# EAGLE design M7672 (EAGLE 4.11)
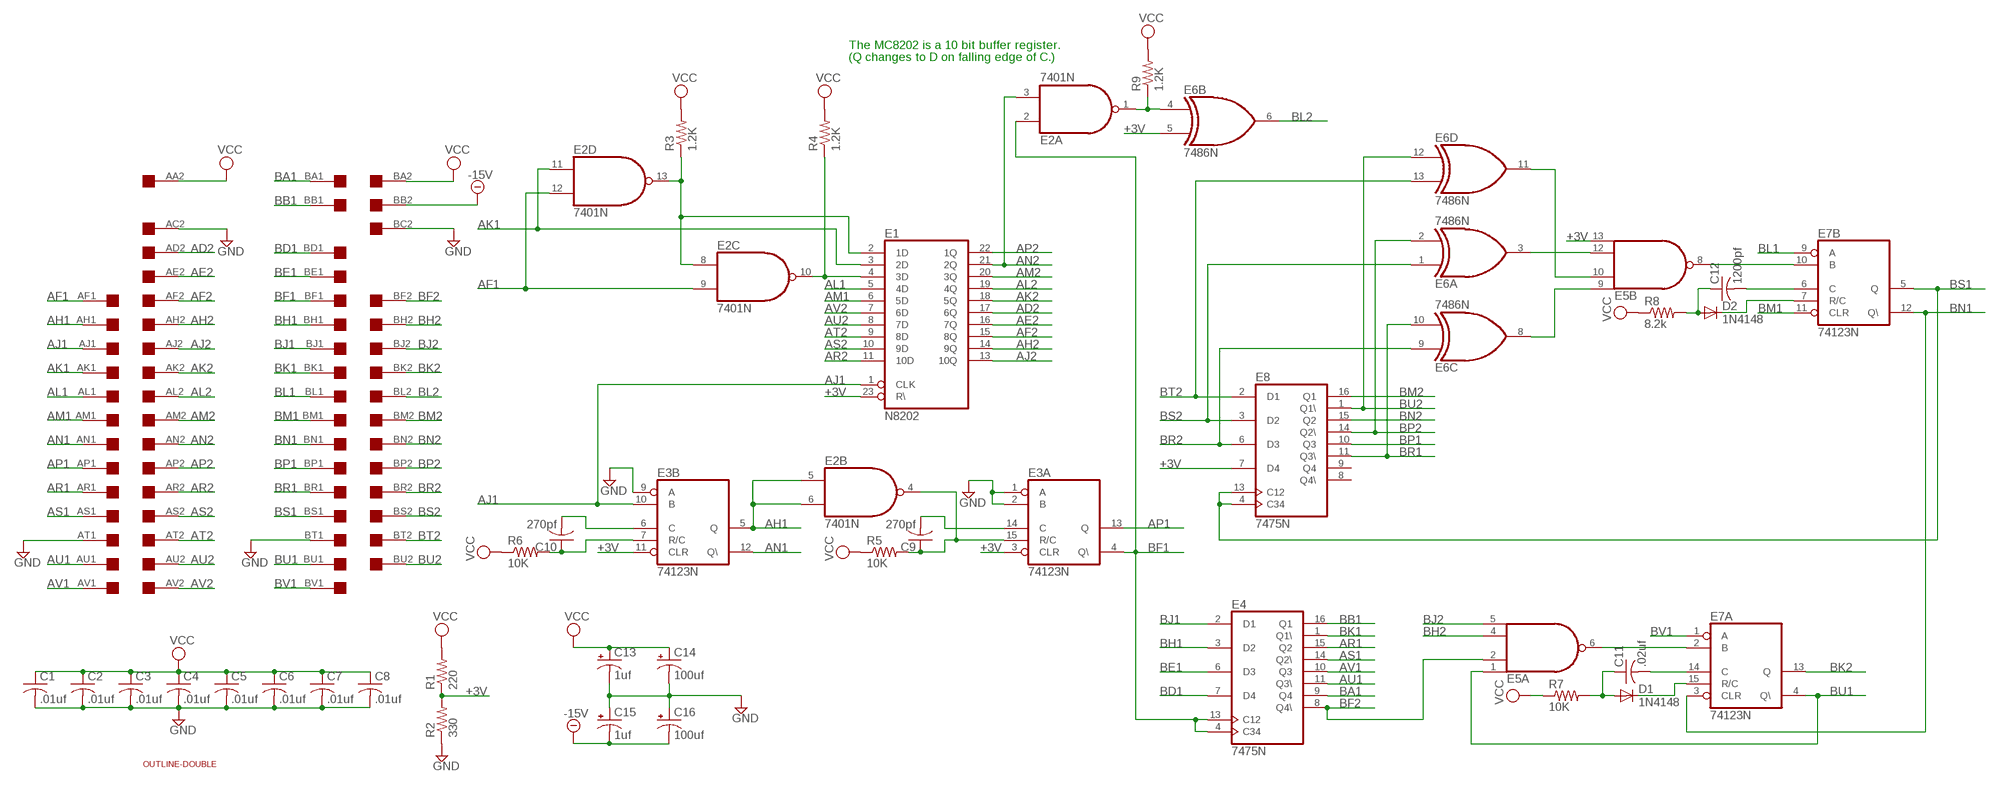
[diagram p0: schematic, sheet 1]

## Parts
C1  .01uf  C-US050-025X075  [C050-025X075]
C2  .01uf  C-US050-025X075  [C050-025X075]
C3  .01uf  C-US050-025X075  [C050-025X075]
C4  .01uf  C-US050-025X075  [C050-025X075]
C5  .01uf  C-US050-025X075  [C050-025X075]
C6  .01uf  C-US050-025X075  [C050-025X075]
C7  .01uf  C-US050-025X075  [C050-025X075]
C8  .01uf  C-US050-025X075  [C050-025X075]
C9  270pf  C-US050-025X075  [C050-025X075]
C10  270pf  C-US050-025X075  [C050-025X075]
C11  .02uf  C-US050-025X075  [C050-025X075]
C12  1200pf  C-US050-025X075  [C050-025X075]
C13  1uf  CPOL-USE30-10AXIAL  [E30-10]
C14  100uf  CPOL-USE30-10AXIAL  [E30-10]
C15  1uf  CPOL-USE30-10AXIAL  [E30-10]
C16  100uf  CPOL-USE30-10AXIAL  [E30-10]
D1  1N4148  [DO35-10]
D2  1N4148  [DO35-10]
E1  N8202  [DIL24]
E2  7401N  [DIL14]
E3  74123N  [DIL16]
E4  7475N  [DIL16]
E5  74S20N  [DIL14]
E6  7486N  [DIL14]
E7  74123N  [DIL16]
E8  7475N  [DIL16]
EDGE  DOUBLE  [EDGE-CON4]
R1  220  R-US_0207/10  [0207/10]
R2  330  R-US_0207/10  [0207/10]
R3  1.2K  R-US_0207/10  [0207/10]
R4  1.2K  R-US_0207/10  [0207/10]
R5  10K  R-US_0207/10  [0207/10]
R6  10K  R-US_0207/10  [0207/10]
R7  10K  R-US_0207/10  [0207/10]
R8  8.2k  R-US_0207/10  [0207/10]
R9  1.2K  R-US_0207/10  [0207/10]
U$2  OUTLINE-DOUBLE  [DOUBLE]

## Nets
+3V: E1.23(R\) E3.3(A:CLR) E3.11(B:CLR) E5.13(B:I3) E6.5(B:I1) E8.7(D4) R1.1 R2.2
-15V: C15.- C16.- EDGE.BB2
AD2: E1.17(6Q) EDGE.AD2
AE2: E1.16(7Q) EDGE.AE2
AF1: E2.9(C:I1) E2.12(D:I1) EDGE.AF1
AF2: E1.15(8Q) EDGE.AF2
AH1: E2.5(B:I0) E2.6(B:I1) E3.5(B:Q) EDGE.AH1
AH2: E1.14(9Q) EDGE.AH2
AJ1: E1.1(CLK) E3.10(B:B) EDGE.AJ1
AJ2: E1.13(10Q) EDGE.AJ2
AK1: E1.3(2D) E2.11(D:I0) EDGE.AK1
AK2: E1.18(5Q) EDGE.AK2
AL1: E1.5(4D) EDGE.AL1
AL2: E1.19(4Q) EDGE.AL2
AM1: E1.6(5D) EDGE.AM1
AM2: E1.20(3Q) EDGE.AM2
AN1: E3.12(B:Q\) EDGE.AN1
AN2: E1.21(2Q) E2.3(A:I1) EDGE.AN2
AP1: E3.13(A:Q) EDGE.AP1
AP2: E1.22(1Q) EDGE.AP2
AR1: E4.15(Q2) EDGE.AR1
AR2: E1.11(10D) EDGE.AR2
AS1: E4.14(Q2\) EDGE.AS1
AS2: E1.10(9D) EDGE.AS2
AT2: E1.9(8D) EDGE.AT2
AU1: E4.11(Q3\) EDGE.AU1
AU2: E1.8(7D) EDGE.AU2
AV1: E4.10(Q3) EDGE.AV1
AV2: E1.7(6D) EDGE.AV2
BA1: E4.9(Q4) EDGE.BA1
BB1: E4.16(Q1) EDGE.BB1
BD1: E4.7(D4) EDGE.BD1
BE1: E4.6(D3) EDGE.BE1
BF1: E2.2(A:I0) E3.4(A:Q\) E4.4(C34) E4.13(C12) EDGE.BF1
BF2: E4.8(Q4\) E5.2(A:I1) EDGE.BF2
BH1: E4.3(D2) EDGE.BH1
BH2: E5.4(A:I2) EDGE.BH2
BJ1: E4.2(D1) EDGE.BJ1
BJ2: E5.5(A:I3) EDGE.BJ2
BK1: E4.1(Q1\) EDGE.BK1
BK2: E7.13(A:Q) EDGE.BK2
BL1: E7.9(B:A) EDGE.BL1
BL2: E6.6(B:O) EDGE.BL2
BM1: E7.11(B:CLR) EDGE.BM1
BM2: E8.16(Q1) EDGE.BM2
BN1: E7.3(A:CLR) E7.12(B:Q\) EDGE.BN1
BN2: E8.15(Q2) EDGE.BN2
BP1: E8.10(Q3) EDGE.BP1
BP2: E6.2(A:I1) E8.14(Q2\) EDGE.BP2
BR1: E6.10(C:I1) E8.11(Q3\) EDGE.BR1
BR2: E6.9(C:I0) E8.6(D3) EDGE.BR2
BS1: E7.5(B:Q) E8.4(C34) E8.13(C12) EDGE.BS1
BS2: E6.1(A:I0) E8.3(D2) EDGE.BS2
BT2: E6.13(D:I1) E8.2(D1) EDGE.BT2
BU1: E5.1(A:I0) E7.4(A:Q\) EDGE.BU1
BU2: E6.12(D:I0) E8.1(Q1\) EDGE.BU2
BV1: E7.1(A:A) EDGE.BV1
GND [power]: C1.2 C2.2 C3.2 C4.2 C5.2 C6.2 C7.2 C8.2 C13.- C14.- C15.+ C16.+ E3.1(A:A) E3.2(A:B) E3.9(B:A) EDGE.AC2 EDGE.AT1 EDGE.BC2 EDGE.BT1 R2.1
N$1: E1.2(1D) E2.8(C:I0) E2.13(D:O) R3.1
N$2: E1.4(3D) E2.10(C:O) R4.1
N$3: E2.1(A:O) E6.4(B:I0) R9.1
N$4: E5.12(B:I2) E6.3(A:O)
N$5: C10.1 E3.7(B:R/C) R6.2
N$6: C10.2 E3.6(B:C)
N$7: C9.1 E2.4(B:O) E3.15(A:R/C) R5.2
N$8: C9.2 E3.14(A:C)
N$9: E5.10(B:I1) E6.11(D:O)
N$10: E5.9(B:I0) E6.8(C:O)
N$12: E5.6(A:O) E7.2(A:B)
N$13: D1.C E7.15(A:R/C)
N$14: C11.2 E7.14(A:C)
N$15: C11.1 D1.A R7.2
N$16: E5.8(B:O) E7.10(B:B)
N$17: D2.C E7.7(B:R/C)
N$18: C12.2 E7.6(B:C)
N$19: C12.1 D2.A R8.2
VCC [power]: C1.1 C2.1 C3.1 C4.1 C5.1 C6.1 C7.1 C8.1 C13.+ C14.+ EDGE.AA2 EDGE.BA2 R1.2 R3.2 R4.2 R5.1 R6.1 R7.1 R8.1 R9.2
Unconnected: E8.8(Q4\) E8.9(Q4) EDGE.AA1 EDGE.AB1 EDGE.AB2 EDGE.AC1 EDGE.AD1 EDGE.AE1 EDGE.BC1 EDGE.BD2 EDGE.BE2 EDGE.BV2

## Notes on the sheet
- The MC8202 is a 10 bit buffer register.
- (Q changes to D on falling edge of C.)

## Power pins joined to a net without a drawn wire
GND: E1.12(GND) E2.7(P:GND) E3.8(P:GND) E4.12(GND) E5.7(P:GND) E6.7(P:GND) E7.8(P:GND) E8.12(GND)
VCC: E1.24(VCC) E2.14(P:VCC) E3.16(P:VCC) E4.5(VCC) E5.14(P:VCC) E6.14(P:VCC) E7.16(P:VCC) E8.5(VCC)

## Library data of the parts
C1-C12 = rcl:C-US: CAPACITOR, American symbol
C13-C16 = rcl:CPOL-US: POLARIZED CAPACITOR, American symbol
D1 D2 = diode:1N4148: DIODE
E1 = dec-con:N8202: 10 bit register
E2 = 74xx-jameco:74*01: Quad 2-input NAND gate, open collector
E3 E7 = 74xx-jameco:74*123: Retriggerable monostable MULTIVIBRATOR
E4 E8 = 74xx-jameco:74*75: 4-bit bistable LATCH
E5 = 74xx-jameco:74*20: Dual 4-input NAND gate
E6 = 74xx-jameco:74*86: Quad 2-input EXCLUSIV-OR (XOR) gate
EDGE = dec-con:DOUBLE: Double-Height DEC board
R1-R9 = rcl:R-US_: RESISTOR, American symbol
U$2 = dec-con:OUTLINE-*: Board outlines for DEC boards.

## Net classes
1 power: width 0.508 mm

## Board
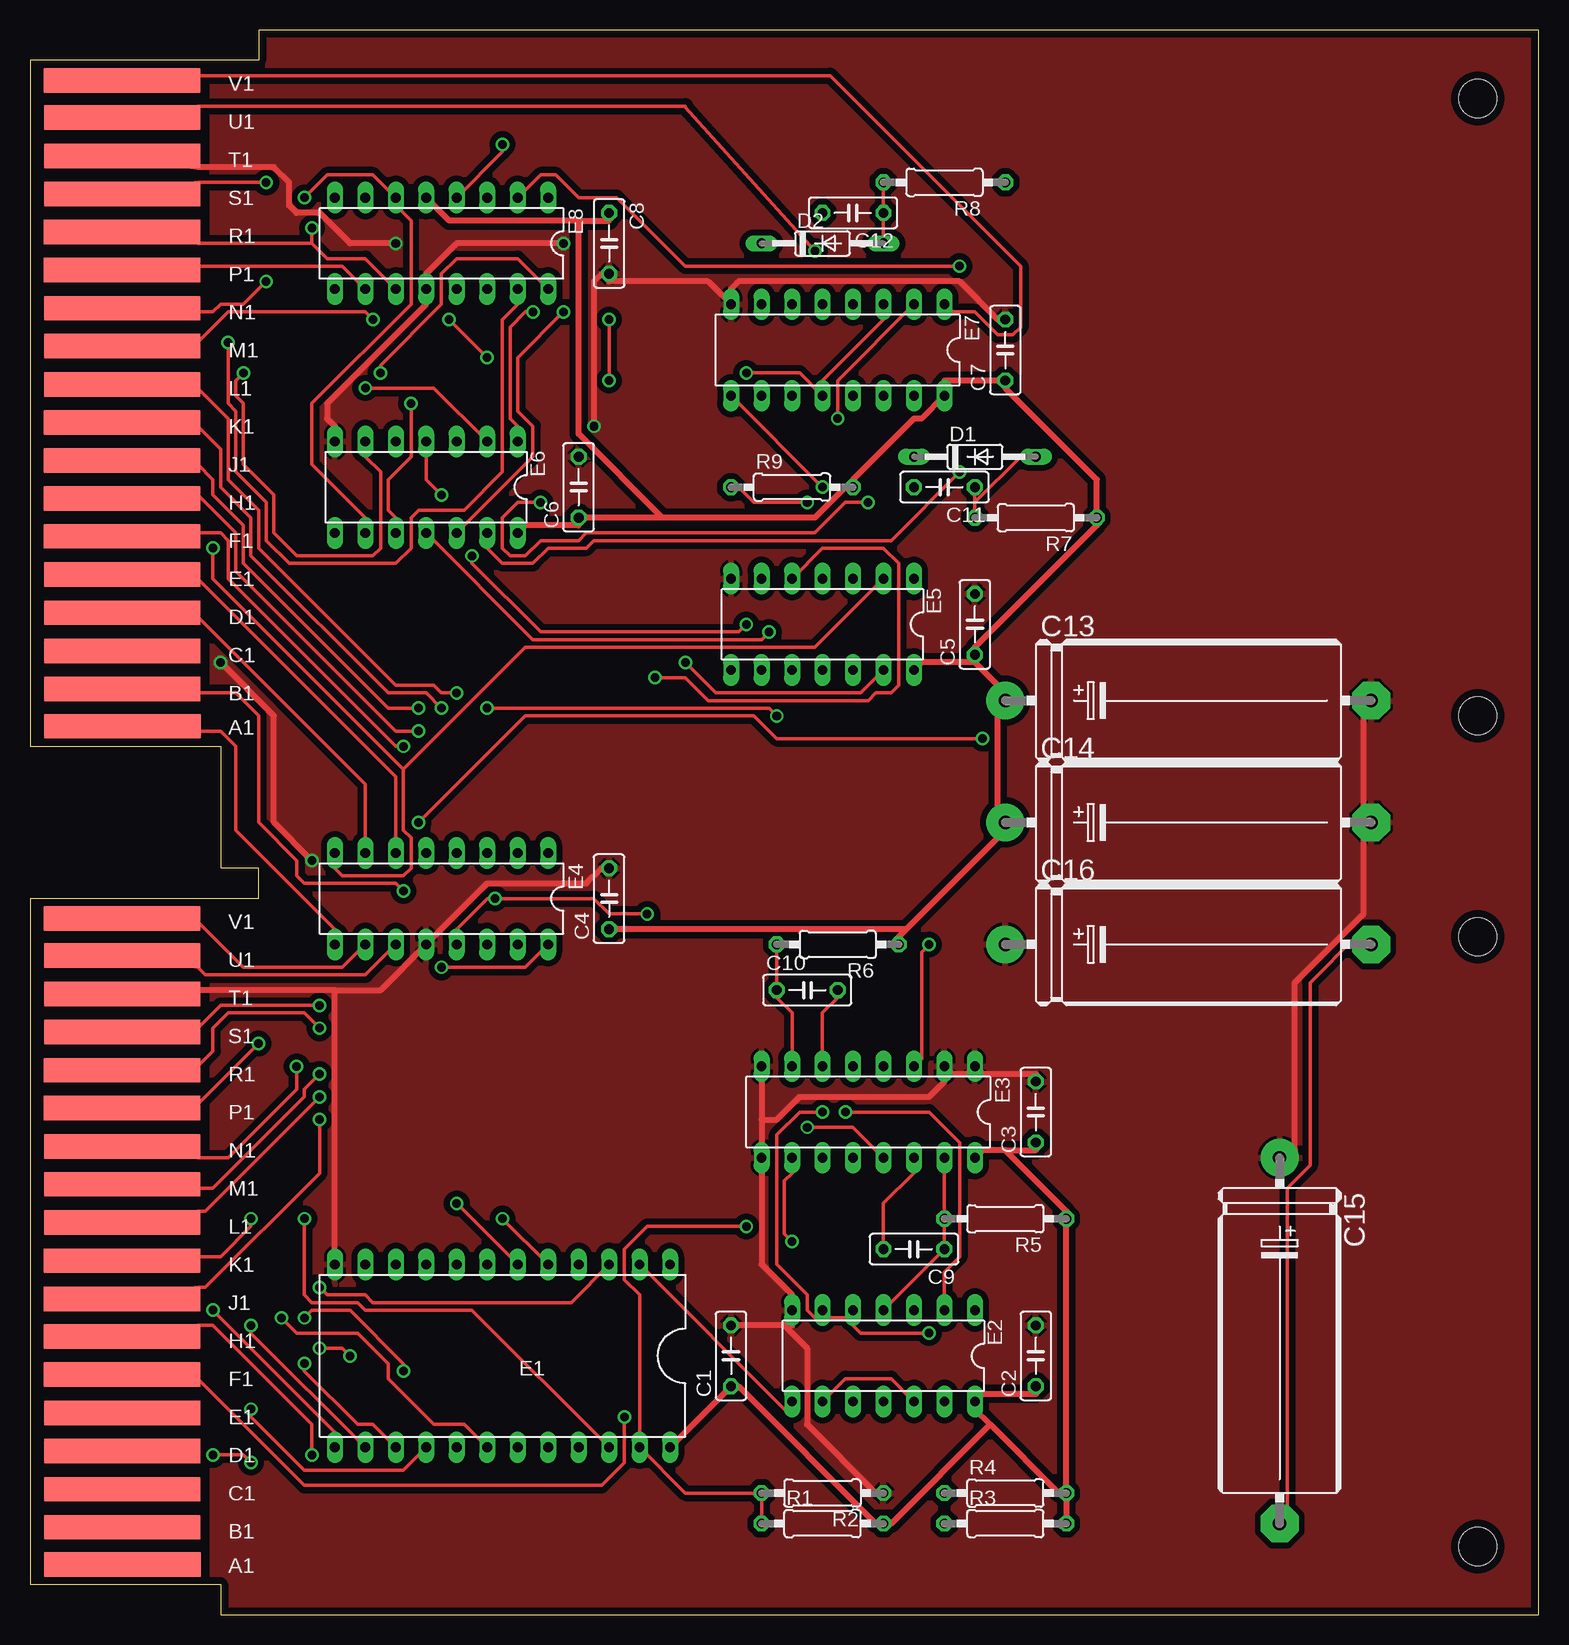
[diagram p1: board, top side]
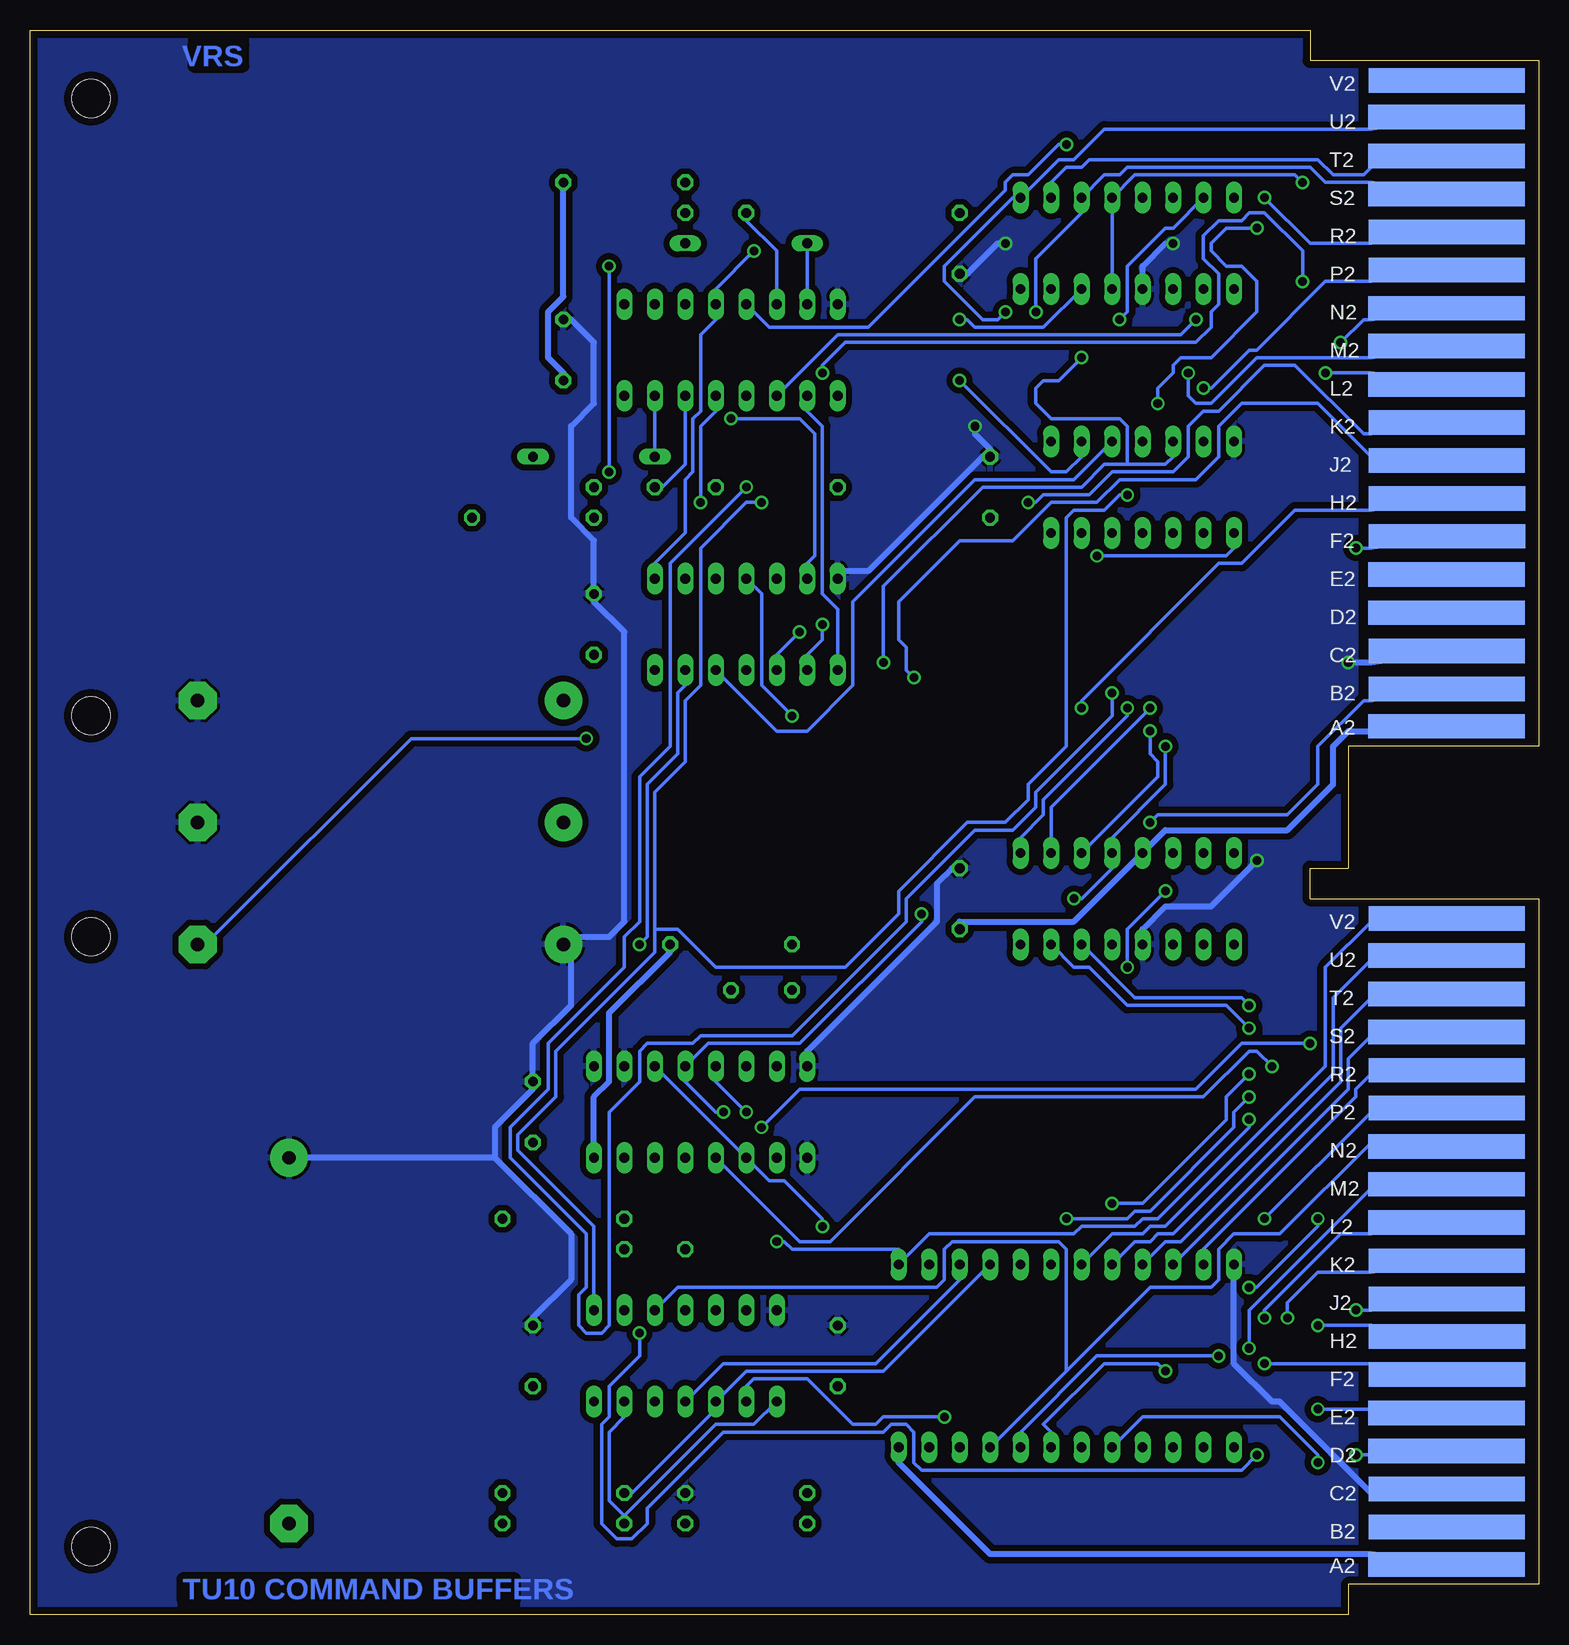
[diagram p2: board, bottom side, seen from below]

Size 125.73 x 132.08 mm. Coordinates in mm from the lower left corner, seen from the top.
Copper layers (1*16): Top 0.035mm / dielectric 1.5mm / Bottom 0.035mm
Design rules "10mils": minimum track width 12mil, minimum drill 28mil, track to track 10mil, track to pad 10mil, pad to pad 10mil, via to via 10mil, smd to smd 10mil, copper to edge 25mil, drill to drill 10mil, minimum pad ring 10mil, minimum via ring 8mil, stop-mask expansion 0mil, vias tented up to drill 0mil, thermal gap 10mil

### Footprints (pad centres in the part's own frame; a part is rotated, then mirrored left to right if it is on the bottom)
C050-025X075 = drill 0.813 octagon: 1 -2.54,0; 2 2.54,0
E30-10 = drill 1.118 pad 3.15 round: + -15.24,0 | drill 1.118 pad 3.15 octagon: - 15.24,0
DO35-10 = drill 0.813 long: A 5.08,0; C -5.08,0
DIL24 = drill 0.813 long: 1 -12.7,-7.62; 2 -10.16,-7.62; 3 -7.62,-7.62; 4 -5.08,-7.62; 5 -2.54,-7.62; 6 0,-7.62; 7 2.54,-7.62; 8 5.08,-7.62; 9 7.62,-7.62; 10 10.16,-7.62; 11 12.7,-7.62; 12 15.24,-7.62; 13 15.24,7.62; 14 12.7,7.62; 15 10.16,7.62; 16 7.62,7.62; 17 5.08,7.62; 18 2.54,7.62; 19 0,7.62; 20 -2.54,7.62; 21 -5.08,7.62; 22 -7.62,7.62; 23 -10.16,7.62; 24 -12.7,7.62
DIL14 = drill 0.813 long: 1 -7.62,-3.81; 2 -5.08,-3.81; 3 -2.54,-3.81; 4 0,-3.81; 5 2.54,-3.81; 6 5.08,-3.81; 7 7.62,-3.81; 8 7.62,3.81; 9 5.08,3.81; 10 2.54,3.81; 11 0,3.81; 12 -2.54,3.81; 13 -5.08,3.81; 14 -7.62,3.81
DIL16 = drill 0.813 long: 1 -8.89,-3.81; 2 -6.35,-3.81; 3 -3.81,-3.81; 4 -1.27,-3.81; 5 1.27,-3.81; 6 3.81,-3.81; 7 6.35,-3.81; 8 8.89,-3.81; 9 8.89,3.81; 10 6.35,3.81; 11 3.81,3.81; 12 1.27,3.81; 13 -1.27,3.81; 14 -3.81,3.81; 15 -6.35,3.81; 16 -8.89,3.81
EDGE-CON4 = smd 13.017 x 2.032: AA1 7.709,4.207; AB1 7.684,7.312; AC1 7.684,10.474; AD1 7.684,13.665; AE1 7.693,16.84; AF1 7.668,20.041; AH1 7.668,23.19; AJ1 7.668,26.34; AK1 7.668,29.515; AL1 7.693,32.69; AM1 7.693,35.89; AN1 7.693,39.04; AP1 7.668,42.24; AR1 7.668,45.39; AS1 7.693,48.565; AT1 7.693,51.74; AU1 7.693,54.94; AV1 7.668,58.026; BA1 7.709,74.057; BB1 7.684,77.162; BC1 7.684,80.324; BD1 7.684,83.515; BE1 7.693,86.69; BF1 7.668,89.891; BH1 7.668,93.04; BJ1 7.668,96.19; BK1 7.668,99.365; BL1 7.693,102.54; BM1 7.693,105.74; BN1 7.693,108.89; BP1 7.668,112.09; BR1 7.668,115.24; BS1 7.693,118.415; BT1 7.693,121.59; BU1 7.693,124.79; BV1 7.668,127.876 | smd 13.017 x 2.032 bottom: AA2 7.69,4.207; AB2 7.668,7.328; AC2 7.668,10.49; AD2 7.693,13.665; AE2 7.693,16.84; AF2 7.642,20.041; AH2 7.642,23.19; AJ2 7.668,26.34; AK2 7.668,29.515; AL2 7.693,32.69; AM2 7.693,35.89; AN2 7.693,39.04; AP2 7.668,42.24; AR2 7.668,45.39; AS2 7.693,48.565; AT2 7.693,51.74; AU2 7.693,54.966; AV2 7.668,58.026; BA2 7.69,74.057; BB2 7.668,77.178; BC2 7.668,80.34; BD2 7.693,83.515; BE2 7.693,86.69; BF2 7.642,89.891; BH2 7.642,93.04; BJ2 7.668,96.19; BK2 7.668,99.365; BL2 7.693,102.54; BM2 7.693,105.74; BN2 7.693,108.89; BP2 7.668,112.09; BR2 7.668,115.24; BS2 7.693,118.415; BT2 7.693,121.59; BU2 7.693,124.816; BV2 7.668,127.876
0207/10 = drill 0.813 octagon: 1 -5.08,0; 2 5.08,0
DOUBLE = hole 3.175: 120.65,56.515; 120.65,5.715; 120.65,74.93; 120.65,126.365

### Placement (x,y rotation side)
C1  58.42,21.59 90 top
C2  83.82,21.59 90 top
C3  83.82,41.91 90 top
C4  48.26,59.69 90 top
C5  78.74,82.55 90 top
C6  45.72,93.98 90 top
C7  81.28,105.41 90 top
C8  48.26,114.3 270 top
C9  73.66,30.48 180 top
C10  64.77,52.07 0 top
C11  76.2,93.98 180 top
C12  68.58,116.84 180 top
C13  96.52,76.2 0 top
C14  96.52,66.04 0 top
C15  104.14,22.86 270 top
C16  96.52,55.88 0 top
D1  78.74,96.52 0 top
D2  66.04,114.3 0 top
E1  40.64,21.59 180 top
E2  71.12,21.59 180 top
E3  69.85,41.91 180 top
E4  34.29,59.69 180 top
E5  66.04,82.55 180 top
E6  33.02,93.98 180 top
E7  67.31,105.41 180 top
E8  34.29,114.3 180 top
EDGE  0,0 0 top
R1  66.04,7.62 0 top
R2  66.04,10.16 180 top
R3  81.28,7.62 0 top
R4  81.28,10.16 0 top
R5  81.28,33.02 180 top
R6  67.31,55.88 180 top
R7  83.82,91.44 180 top
R8  76.2,119.38 180 top
R9  63.5,93.98 0 top
U$2  0,0 0 top

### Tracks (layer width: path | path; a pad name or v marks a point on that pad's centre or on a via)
+3V  (via drill 0.71)
  Top 0.305: R1.1 R2.2 54.61,10.16 E1.23 50.8,26.67 49.53,27.94 49.53,30.48 51.44,32.38 v59.69,32.38 | v74.93,55.88 74.3,55.24 74.3,46.35 E3.3 | v54.61,79.38 57.15,76.83 69.22,76.83 E5.13 | v38.1,104.78 v34.93,107.95
  Bottom 0.305: E3.3 E3.11 64.14,36.2 62.87,36.2 59.69,33.02 v59.69,32.38 | v74.93,55.88 74.3,56.52 74.3,69.22 71.76,71.75 71.76,76.83 71.12,77.47 E5.13 | 34.29,95.89 36.2,95.89 38.1,93.98 46.36,93.98 54.61,85.72 v54.61,79.38 | 34.29,95.89 31.12,95.89 30.48,96.52 E6.5 | v34.93,107.95 34.29,108.58 34.29,112.39 31.12,115.57 30.48,115.57 E8.7 | v38.1,104.78 40.01,102.87 41.28,102.87 41.91,102.23 41.91,100.97 40.64,99.69 34.93,99.69 34.29,99.06 34.29,95.89
-15V  (via drill 0.71)
  Top 0.305: C15.- 104.78,8.89 104.78,35.56 106.68,37.47 106.68,52.7 110.49,56.52 C16.- | v32.39,66.04 41.28,74.93 60.33,74.93 62.23,73.03 v79.38,73.03
  Bottom 0.305: v32.39,66.04 31.75,66.67 20.96,66.67 18.42,69.22 18.42,72.39 14.61,76.2 13.97,76.2 EDGE.BB2 | v79.38,73.03 93.98,73.03 110.49,56.52 C16.-
AD2  (via drill 0.71)
  Top 0.305: v15.24,13.34 17.78,13.34 v18.42,12.7
  Bottom 0.305: v15.24,13.34 13.97,13.34 EDGE.AD2 | v18.42,12.7 18.42,13.34 21.59,16.51 33.02,16.51 E1.17
AE2  (via drill 0.71)
  Top 0.305: v18.42,17.14 18.42,16.51 22.86,12.06 31.12,12.06 E1.16
  Bottom 0.305: v18.42,17.14 13.97,17.14 EDGE.AE2
AF1  (via drill 0.71)
  Top 0.305: E2.9 67.95,19.68 71.76,19.68 E2.12 | v49.53,16.51 49.53,12.7 47.63,10.79 22.86,10.79 13.97,19.68 EDGE.AF1
  Bottom 0.305: v49.53,16.51 54.61,16.51 55.25,15.88 57.15,15.88 60.96,19.68 65.41,19.68 66.04,19.05 E2.9
AF2  (via drill 0.71)
  Top 0.305: v22.86,20.95 22.86,20.32 27.31,15.88 28.58,15.88 E1.15
  Bottom 0.305: v22.86,20.95 13.97,20.95 EDGE.AF2
AH1  (via drill 0.71)
  Top 0.305: v66.04,41.91 64.14,41.91 62.23,40.01 62.23,29.21 64.77,26.67 64.77,25.4 65.41,24.77 E2.6 66.68,24.77 67.95,24.77 E2.5 68.58,24.13 69.22,23.5 v74.93,23.5 | v23.5,13.34 23.5,15.88 15.24,24.13 13.97,24.13 EDGE.AH1
  Bottom 0.305: v66.04,41.91 68.58,44.45 E3.5 | v74.93,23.5 74.93,21.59 77.47,19.05 77.47,16.51 78.11,15.88 78.11,7.62 76.84,6.35 75.57,6.35 74.3,7.62 74.3,8.89 67.95,15.24 54.61,15.24 53.98,15.88 52.71,15.88 52.07,15.24 52.07,12.7 51.44,12.06 24.77,12.06 v23.5,13.34
AH2  (via drill 0.71)
  Top 0.305: v18.42,24.13 18.42,23.5 E1.14
  Bottom 0.305: v18.42,24.13 13.97,24.13 EDGE.AH2
AJ1  (via drill 0.71)
  Top 0.305: v24.13,41.27 24.13,36.83 14.61,27.3 13.97,27.3 EDGE.AJ1 | v63.5,31.11 62.87,31.75 62.87,36.2 63.5,36.83 E3.10
  Bottom 0.305: v24.13,41.27 24.13,40.64 31.75,33.02 33.02,33.02 33.66,32.38 38.1,32.38 38.74,31.75 50.8,31.75 E1.1 53.34,30.48 62.23,30.48 62.87,31.11 v63.5,31.11
AJ2  (via drill 0.71)
  Top 0.305: v15.24,25.4 25.4,15.24 E1.13
  Bottom 0.305: v15.24,25.4 13.97,25.4 EDGE.AJ2
AK1  (via drill 0.71)
  Top 0.305: v18.42,33.02 18.42,32.38 15.88,29.84 13.97,29.84 EDGE.AK1 | v24.13,27.3 24.77,26.67 27.94,26.67 28.58,26.04 45.09,26.04 E1.3
  Bottom 0.305: v18.42,33.02 18.42,32.38 23.5,27.3 v24.13,27.3 | E2.11 67.95,20.95 55.25,20.95 48.26,27.94 E1.3
AK2  (via drill 0.71)
  Top 0.305: v20.96,24.77 22.23,23.5 27.31,23.5 29.85,20.95 29.85,19.68 33.66,15.88 36.2,15.88 E1.18
  Bottom 0.305: v20.96,24.77 20.96,26.04 18.42,28.57 13.97,28.57 EDGE.AK2
AL1  (via drill 0.71)
  Top 0.305: v24.13,43.18 14.61,33.66 13.97,33.66 EDGE.AL1 | v39.37,33.02 E1.5
  Bottom 0.305: v24.13,43.18 25.4,41.91 25.4,40.64 32.39,33.66 33.66,33.66 34.29,33.02 v39.37,33.02
AL2  (via drill 0.71)
  Top 0.305: v22.86,24.77 23.5,25.4 26.67,25.4 31.12,20.95 v31.12,20.32
  Bottom 0.305: v22.86,24.77 22.86,25.4 16.51,31.75 13.97,31.75 EDGE.AL2 | v31.12,20.32 31.75,20.95 36.2,20.95 41.28,15.88 40.64,15.24 E1.19
AM1  (via drill 0.71)
  Top 0.305: v24.13,45.09 22.86,43.81 22.86,43.18 15.24,35.56 13.97,35.56 EDGE.AM1 | v35.56,34.29 E1.6
  Bottom 0.305: v24.13,45.09 26.04,43.18 26.04,41.27 33.02,34.29 v35.56,34.29
AM2  (via drill 0.71)
  Top 0.305: v26.67,21.59 26.04,22.23 v24.13,22.23
  Bottom 0.305: v26.67,21.59 36.83,21.59 43.18,15.24 E1.20 | v24.13,22.23 24.13,25.4 13.97,35.56 EDGE.AM2
AN1  (via drill 0.71)
  Top 0.305: v22.23,45.72 22.23,43.81 16.51,38.1 13.97,38.1 EDGE.AN1
  Bottom 0.305: v22.23,45.72 23.5,46.99 24.13,46.99 27.94,43.18 46.99,43.18 59.06,31.11 61.6,31.11 E3.12
AN2
  Bottom 0.305: 39.37,20.32 32.39,27.3 27.31,27.3 26.67,27.94 26.67,30.48 25.4,31.75 21.59,31.75 13.97,39.37 EDGE.AN2 | 39.37,20.32 E1.21 | 39.37,20.32 39.37,30.48 40.01,31.11 48.9,31.11 49.53,30.48 49.53,27.94 50.17,27.3 71.76,27.3 E2.3
AP1  (via drill 0.71)
  Top 0.305: v64.77,40.64 68.58,40.64 E3.13 | v19.05,47.62 13.97,42.55 EDGE.AP1
  Bottom 0.305: v64.77,40.64 61.6,43.81 28.58,43.81 24.77,47.62 v19.05,47.62
AP2  (via drill 0.71)
  Top 0.305: v22.86,33.02 22.86,26.67 23.5,26.04 27.31,26.04 27.94,25.4 36.83,25.4 E1.22
  Bottom 0.305: v22.86,33.02 13.97,41.91 EDGE.AP2
AR1  (via drill 0.71)
  Top 0.305: v24.13,48.9 22.86,50.16 16.51,50.16 15.24,48.9 15.24,46.99 13.97,45.72 EDGE.AR1
  Bottom 0.305: v24.13,48.9 26.04,50.8 34.29,50.8 37.47,53.98 38.74,53.98 E4.15
AR2
  Bottom 0.305: E1.11 27.94,30.48 15.24,43.18 15.24,43.81 13.97,45.09 EDGE.AR2
AS1  (via drill 0.71)
  Top 0.305: v24.13,50.8 15.88,50.8 13.97,48.9 EDGE.AS1
  Bottom 0.305: v24.13,50.8 24.77,51.44 33.66,51.44 E4.14
AS2
  Bottom 0.305: E1.10 15.88,43.81 15.88,46.35 13.97,48.26 EDGE.AS2
AT2
  Bottom 0.305: E1.9 31.12,31.11 29.85,31.11 16.51,44.45 16.51,48.9 13.97,51.44 EDGE.AT2
AU1
  Top 0.305: E4.11 27.94,53.34 14.61,53.34 13.97,53.98 EDGE.AU1
AU2
  Bottom 0.305: E1.8 33.66,31.11 32.39,31.11 31.75,31.75 30.48,31.75 17.15,45.09 17.15,51.44 13.97,54.61 EDGE.AU2
AV1
  Top 0.305: E4.10 26.04,53.98 17.78,53.98 13.97,57.78 EDGE.AV1
AV2
  Bottom 0.305: E1.7 35.56,31.75 33.02,31.75 32.39,32.38 31.12,32.38 17.78,45.72 17.78,53.98 13.97,57.78 EDGE.AV2
BA1
  Top 0.305: E4.9 25.4,57.15 17.15,65.41 17.15,72.39 15.88,73.66 13.97,73.66 EDGE.BA1
BB1  (via drill 0.71)
  Top 0.305: v34.29,53.98 41.28,53.98 E4.16 | v31.12,60.33 30.48,60.96 22.86,60.96 22.23,61.59 22.23,62.87 19.05,66.04 19.05,74.93 17.15,76.83 13.97,76.83 EDGE.BB1
  Bottom 0.305: v34.29,53.98 34.29,57.15 v31.12,60.33
BD1
  Top 0.305: E4.7 27.94,69.22 13.97,83.19 EDGE.BD1
BE1
  Top 0.305: E4.6 30.48,69.85 13.97,86.36 EDGE.BE1
BF1  (via drill 0.71)
  Top 0.305: E4.13 35.56,57.15 38.1,59.69 v38.74,59.69 46.99,59.69 48.26,58.42 v51.44,58.42 | v67.95,41.91 74.93,41.91 77.47,39.37 77.47,29.84 76.2,28.57 E2.2 | v31.12,72.39 30.48,72.39 16.51,86.36 16.51,89.53 15.88,90.17 13.97,90.17 EDGE.BF1
  Bottom 0.305: v38.74,59.69 38.1,59.69 35.56,62.23 E4.4 35.56,64.77 31.12,69.22 v31.12,72.39 | v67.95,41.91 68.58,41.91 71.12,44.45 E3.4 69.22,47.62 61.6,47.62 51.44,57.78 v51.44,58.42
BF2  (via drill 0.71)
  Top 0.305: v15.24,88.9 15.24,86.36 31.12,70.48 | 31.12,70.48 31.12,65.41 31.75,64.77 31.75,62.23 31.12,61.59 26.04,61.59 25.4,62.23 E4.8 | 31.12,70.48 41.28,80.64 65.41,80.64 E5.2
  Bottom 0.305: v15.24,88.9 13.97,88.9 EDGE.BF2
BH1  (via drill 0.71)
  Top 0.305: v32.39,73.66 30.48,73.66 17.15,87 17.15,90.17 13.97,93.34 EDGE.BH1
  Bottom 0.305: v32.39,73.66 32.39,71.75 31.75,71.12 31.75,69.85 E4.3
BH2  (via drill 0.71)
  Top 0.305: v38.1,75.56 61.6,75.56 v62.23,74.93
  Bottom 0.305: v38.1,75.56 38.1,76.2 26.67,87.63 24.77,87.63 20.32,92.08 13.97,92.08 EDGE.BH2 | v62.23,74.93 64.77,77.47 64.77,85.09 E5.4
BJ1  (via drill 0.71)
  Top 0.305: v32.39,75.56 29.85,75.56 17.78,87.63 17.78,90.81 15.24,93.34 15.24,94.61 13.97,95.89 EDGE.BJ1
  Bottom 0.305: v32.39,75.56 40.64,67.31 E4.2
BJ2  (via drill 0.71)
  Top 0.305: v52.07,78.11 54.61,78.11 56.52,76.2 69.85,76.2 70.49,76.83 71.76,76.83 72.39,77.47 72.39,87.63 71.12,88.9 66.04,88.9 E5.5
  Bottom 0.305: v52.07,78.11 52.71,78.74 52.71,80.64 53.34,81.28 53.34,84.45 48.26,89.53 43.82,89.53 40.64,92.71 36.83,92.71 34.93,94.61 28.58,94.61 26.67,96.52 26.67,99.06 24.77,100.97 18.42,100.97 13.97,96.52 EDGE.BJ2
BK1  (via drill 0.71)
  Top 0.305: v34.29,75.56 33.02,76.83 29.85,76.83 18.42,88.27 18.42,91.44 15.88,93.98 15.88,97.16 13.97,99.06 EDGE.BK1
  Bottom 0.305: v34.29,75.56 34.29,74.93 41.28,67.94 41.28,66.67 43.18,64.77 E4.1
BK2  (via drill 0.71)
  Top 0.305: v69.85,92.71 67.95,92.71 65.41,90.17 46.36,90.17 45.72,89.53 42.55,89.53 41.28,88.27 40.01,88.27 39.37,88.9 39.37,91.44 40.64,92.71 v42.55,92.71
  Bottom 0.305: v69.85,92.71 69.85,99.06 68.58,100.33 E7.13 | v42.55,92.71 41.91,92.71 41.28,93.34 37.47,93.34 35.56,95.25 30.48,95.25 29.21,96.52 29.21,99.06 27.94,100.33 26.67,100.33 22.86,104.14 20.32,104.14 14.61,98.42 13.97,98.42 EDGE.BK2
BL1  (via drill 0.71)
  Top 0.305: v35.56,76.83 34.29,76.83 33.66,77.47 30.48,77.47 19.05,88.9 19.05,92.08 16.51,94.61 16.51,99.69 13.97,102.23 EDGE.BL1 | v66.04,93.98 E7.9
  Bottom 0.305: v66.04,93.98 72.39,87.63 72.39,72.39 74.93,69.85 74.93,57.78 76.2,56.52 76.2,53.98 82.55,47.62 82.55,43.81 85.73,40.64 85.73,38.1 79.38,31.75 79.38,27.3 80.01,26.67 80.01,24.13 79.38,23.5 78.11,23.5 77.47,24.13 77.47,41.91 74.93,44.45 74.93,46.99 74.3,47.62 70.49,47.62 69.85,48.26 62.23,48.26 52.71,57.78 52.71,59.69 46.99,65.41 43.82,65.41 41.91,67.31 41.91,68.58 35.56,74.93 v35.56,76.83
BL2  (via drill 0.71)
  Top 0.305: v17.78,103.5 17.15,102.87 17.15,101.6 17.78,100.97 17.78,95.89 20.32,93.34 20.32,90.17 22.23,88.27 28.58,88.27 29.21,88.9 29.21,95.25 27.94,96.52 E6.6
  Bottom 0.305: v17.78,103.5 13.97,103.5 EDGE.BL2
BM1  (via drill 0.71)
  Top 0.305: v28.58,107.95 27.94,108.58 16.51,108.58 13.97,106.05 EDGE.BM1
  Bottom 0.305: v28.58,107.95 29.85,106.68 58.42,106.68 E7.11
BM2  (via drill 0.71)
  Top 0.305: v29.21,103.5 29.21,104.14 34.29,109.22 34.29,111.76 35.56,113.03 40.64,113.03 E8.16
  Bottom 0.305: v29.21,103.5 29.21,101.6 28.58,100.97 27.31,100.97 23.5,104.78 13.97,104.78 EDGE.BM2
BN1  (via drill 0.71)
  Top 0.305: v19.69,111.12 17.78,109.22 15.88,109.22 15.24,108.58 13.97,108.58 EDGE.BN1 | v59.69,103.5 64.14,103.5 E7.12 66.04,102.87 71.12,107.95 E7.3
  Bottom 0.305: v19.69,111.12 19.69,113.67 22.86,116.84 24.13,116.84 24.77,116.2 26.67,116.2 27.94,114.94 27.94,113.03 26.67,111.76 26.67,109.22 27.31,108.58 27.31,107.31 28.58,106.05 57.79,106.05 59.69,104.14 v59.69,103.5
BN2  (via drill 0.71)
  Top 0.305: v16.51,106.05 16.51,100.97 17.15,100.33 17.15,95.25 19.69,92.71 19.69,89.53 21.59,87.63 30.48,87.63 31.75,88.9 31.75,91.44 32.39,92.08 36.2,92.08 39.37,95.25 39.37,107.95 40.64,109.22 E8.15
  Bottom 0.305: v16.51,106.05 14.61,107.95 13.97,107.95 EDGE.BN2
BP1
  Top 0.305: E8.10 26.04,112.39 13.97,112.39 EDGE.BP1
BP2  (via drill 0.71)
  Top 0.305: v27.94,102.23 33.66,102.23 E6.2 | v48.26,102.87 v48.26,107.95
  Bottom 0.305: v27.94,102.23 27.31,102.23 24.13,105.41 23.5,105.41 17.78,111.12 13.97,111.12 EDGE.BP2 | v48.26,107.95 47.63,107.95 46.99,107.31 41.28,107.31 E8.14 | v48.26,102.87 40.64,95.25 39.37,95.25 38.1,96.52 E6.2
BR1  (via drill 0.71)
  Top 0.305: 23.5,114.3 13.97,114.3 EDGE.BR1 | 23.5,114.3 24.77,113.03 27.94,113.03 E8.11 | v31.75,100.97 31.75,96.52 29.85,94.61 29.85,92.08 30.48,91.44 E6.10 | v23.5,115.57 23.5,114.3
  Bottom 0.305: v31.75,100.97 31.75,102.23 30.48,103.5 30.48,104.14 29.85,104.78 27.31,104.78 23.5,108.58 23.5,111.12 24.77,112.39 26.04,112.39 27.31,113.67 27.31,114.3 26.04,115.57 v23.5,115.57
BR2  (via drill 0.71)
  Top 0.305: v22.86,118.11 24.77,120.02 28.58,120.02 E8.6 30.48,117.47 31.75,116.2 31.75,109.22 23.5,100.97 23.5,95.89 27.94,91.44 E6.9
  Bottom 0.305: v22.86,118.11 19.05,114.3 13.97,114.3 EDGE.BR2
BS1  (via drill 0.71)
  Top 0.305: v19.69,119.38 13.97,119.38 EDGE.BS1 | v39.37,122.56 39.37,121.92 E8.4
  Bottom 0.305: v19.69,119.38 20.32,120.02 33.66,120.02 E8.4 E8.13 | v39.37,122.56 40.01,122.56 42.55,120.02 43.82,120.02 44.45,119.38 44.45,118.75 55.88,107.31 64.14,107.31 E7.5
BS2  (via drill 0.71)
  Top 0.305: v41.91,108.58 41.28,108.58 40.01,107.31 40.01,99.69 40.64,99.06 E6.1
  Bottom 0.305: EDGE.BS2 13.97,119.38 17.78,119.38 19.05,120.65 34.29,120.65 34.93,120.02 36.2,120.02 E8.3 38.1,116.84 41.91,113.03 v41.91,108.58
BT2  (via drill 0.71)
  Top 0.305: v77.47,95.25 71.76,89.53 46.99,89.53 46.36,88.9 43.18,88.9 41.91,87.63 39.37,87.63 38.1,88.9 E6.13 | v77.47,112.39 54.61,112.39 48.9,118.11 45.72,118.11 43.82,120.02 42.55,120.02 E8.2
  Bottom 0.305: EDGE.BT2 13.97,120.65 14.61,120.02 17.15,120.02 18.42,121.28 37.47,121.28 38.1,120.65 39.37,120.65 40.64,119.38 E8.2 | v77.47,95.25 v77.47,112.39
BU1  (via drill 0.71)
  Top 0.305: v65.41,113.67 54.58,125.7 54.61,125.73 13.97,125.73 EDGE.BU1
  Bottom 0.305: E5.1 73.66,87.63 71.12,90.17 71.12,94.61 70.49,95.25 70.49,99.69 69.85,100.33 69.85,106.68 68.58,107.95 E7.4 68.58,110.49 v65.41,113.67
BU2  (via drill 0.71)
  Top 0.305: v44.45,108.58 40.64,104.78 40.64,100.33 41.91,99.06 41.91,96.52 E6.12
  Bottom 0.305: EDGE.BU2 13.97,123.83 36.2,123.83 38.74,121.28 40.01,121.28 E8.1 43.82,118.11 49.53,112.39 49.53,111.12 46.36,107.95 45.09,107.95 v44.45,108.58
BV1
  Top 0.305: E7.1 76.84,108.58 78.74,108.58 80.65,106.68 81.92,106.68 82.55,107.31 82.55,112.39 66.68,128.27 13.97,128.27 EDGE.BV1
GND  (via drill 0.71)
  Top 0.508: v46.99,99.06 46.99,111.12 47.63,111.76 C8.2 48.26,111.12 56.52,111.12 E7.8 58.42,110.49 59.06,111.12 77.47,111.12 80.65,107.95 C7.2 | v30.48,114.3 26.67,114.3 24.13,116.84 22.23,116.84 21.59,117.47 21.59,119.38 20.32,120.65 13.97,120.65 EDGE.BT1 | E6.7 25.4,99.06 24.77,99.69 24.77,100.97 33.02,109.22 E8.12 33.02,111.76 35.56,114.3 v44.45,114.3 | 60.96,41.27 E3.9 60.96,29.21 63.5,26.67 E2.7 63.5,24.13 62.87,24.13 | E3.8 60.96,41.27 | 62.87,24.13 C1.2 | 62.87,24.13 64.77,22.23 64.77,15.88 70.49,10.16 R2.1 | C13.- 111.13,74.93 111.13,67.31 C14.- 111.13,64.77 111.13,58.42 105.41,52.7 105.41,38.73 C15.+ | C3.2 83.82,45.09 79.38,45.09 E3.1 78.11,45.09 76.84,45.09 E3.2 76.2,44.45 74.93,43.18 64.14,43.18 62.23,41.27 60.96,41.27 | 25.4,52.07 13.97,52.07 EDGE.AT1 | 25.4,52.07 29.21,52.07 E4.12 38.1,60.96 46.36,60.96 47.63,62.23 C4.2 | v15.88,79.38 20.32,74.93 20.32,66.04 v23.5,62.87 | E1.12 25.4,52.07
  Bottom 0.508: C7.2 80.65,107.95 78.74,106.05 78.74,100.97 80.65,99.06 80.65,91.44 78.74,89.53 C5.2 78.74,84.45 76.2,81.92 76.2,57.78 77.47,56.52 80.01,56.52 C16.+ 80.65,54.61 80.65,50.8 83.82,47.62 C3.2 83.82,43.81 87,40.64 87,38.1 | v46.99,99.06 46.99,98.42 45.72,97.16 C6.2 46.36,96.52 55.88,87 57.79,87 E5.7 | v30.48,114.3 31.12,114.3 33.02,112.39 E8.12 | v44.45,114.3 45.09,114.3 47.63,111.76 C8.2 | 87,38.1 80.65,31.75 80.65,27.94 83.82,24.77 C2.2 | 87,38.1 C15.+ | E1.12 25.4,20.95 22.23,17.78 21.59,17.78 13.97,10.16 EDGE.AC2 | v15.88,79.38 13.97,79.38 EDGE.BC2 | v23.5,62.87 27.31,59.05 31.12,59.05 33.02,57.15 E4.12 | E3.8 60.96,46.99 50.17,57.78 50.17,60.96 48.9,62.23 C4.2
  pour Bottom (isolate 0.508): 125.73,0 15.24,0 15.24,132.08 125.73,132.08
  pour Top (isolate 0.508): 125.73,0 15.24,0 15.24,132.08 125.73,132.08
N$1
  Top 0.305: E1.2 62.87,17.14 E2.8
  Bottom 0.305: 76.2,8.26 77.47,9.53 77.47,15.24 76.2,16.51 E2.13 | 76.2,8.26 68.58,15.88 65.41,15.88 E2.8 | 76.2,8.26 R3.1
N$2
  Bottom 0.305: E1.4 54.61,20.32 66.04,20.32 E2.10 68.58,17.14 75.57,10.16 R4.1
N$3  (via drill 0.71)
  Top 0.305: v64.77,92.71 60.33,92.71 59.06,93.98 R9.1 | v34.29,93.34 33.02,94.61 E6.4
  Bottom 0.305: v64.77,92.71 66.04,92.71 69.85,88.9 69.85,77.47 71.12,76.2 71.12,71.12 73.66,68.58 73.66,57.15 | 73.66,57.15 73.66,55.24 81.92,46.99 81.92,43.18 85.09,40.01 85.09,38.73 78.74,32.38 E2.1 | v34.29,93.34 34.93,93.34 36.2,92.08 38.74,92.08 39.37,91.44 39.37,72.39 42.55,69.22 42.55,67.94 44.45,66.04 47.63,66.04 53.34,60.33 53.34,58.42 57.79,53.98 68.58,53.98 71.76,57.15 73.66,57.15
N$4
  Bottom 0.305: E6.3 38.74,94.61 46.99,94.61 57.15,84.45 57.15,77.47 60.96,73.66 63.5,73.66 E5.12
N$5
  Top 0.305: E3.7 63.5,50.16 62.23,51.44 C10.1 R6.2
N$6
  Top 0.305: E3.6 66.04,50.16 67.31,51.44 C10.2
N$7
  Top 0.305: E2.4 C9.1 R5.2 E3.15
N$8
  Top 0.305: C9.2 71.12,34.29 73.66,36.83 E3.14
N$9  (via drill 0.71)
  Top 0.305: v61.6,81.92 60.96,81.28 41.91,81.28 E6.11
  Bottom 0.305: v61.6,81.92 63.5,80.01 E5.10
N$10  (via drill 0.71)
  Top 0.305: v59.69,82.55 59.06,81.92 42.55,81.92 36.83,87.63 v36.83,88.27
  Bottom 0.305: v59.69,82.55 59.69,81.28 60.96,80.01 E5.9 | v36.83,88.27 26.04,88.27 25.4,88.9 E6.8
N$12  (via drill 0.71)
  Top 0.305: v67.31,99.69 67.31,102.87 E7.2
  Bottom 0.305: v67.31,99.69 61.6,99.69 60.33,98.42 60.33,88.27 60.96,87.63 E5.6
N$13
  Bottom 0.305: D1.C E7.15
N$14
  Bottom 0.305: C11.2 73.03,93.98 71.12,95.89 E7.14
N$15
  Top 0.305: R7.2 78.74,92.71 | 78.74,92.71 C11.1 | 78.74,92.71 82.55,96.52 D1.A
N$16
  Bottom 0.305: E5.8 58.42,83.82 59.69,85.09 59.69,99.06 60.96,100.33 E7.10
N$17
  Bottom 0.305: E7.7 D2.C
N$18
  Bottom 0.305: E7.6 63.5,113.67 66.04,116.2 C12.2
N$19
  Top 0.305: D2.A C12.1 R8.2
VCC
  Top 0.508: E1.24 C1.1 59.06,19.05 70.49,7.62 R1.2 71.76,7.62 80.01,15.88 | 81.28,38.73 83.82,38.73 C3.1 | 81.28,38.73 79.38,38.73 E3.16 | 81.28,38.73 86.36,33.66 R5.1 R4.2 | R4.2 R3.2 | C2.1 83.82,18.41 79.38,18.41 E2.14 78.74,17.14 80.01,15.88 | 80.01,15.88 85.73,10.16 R4.2 | 45.72,116.2 48.26,116.2 C8.1 | 45.72,116.2 34.93,116.2 E8.5 | E6.14 41.28,90.81 45.72,90.81 C6.1 52.71,91.44 | 52.71,91.44 65.41,91.44 67.95,93.98 R9.2 68.58,94.61 73.66,99.69 74.3,99.69 E7.16 76.2,102.87 C7.1 81.28,102.23 88.9,94.61 R7.1 88.9,90.81 78.74,80.64 C5.1 78.74,79.38 | 45.72,116.2 45.72,98.42 52.71,91.44 | 78.74,79.38 74.3,79.38 E5.14 | 78.74,79.38 80.65,77.47 C13.+ 80.65,74.93 80.65,67.31 C14.+ 80.65,64.77 73.03,57.15 | 73.03,57.15 72.39,56.52 R6.1 | 73.03,57.15 C4.1
  Bottom 0.508: EDGE.AA2 13.97,5.08 45.72,5.08 53.34,12.7 E1.24 | R8.1 81.28,109.86 82.55,108.58 82.55,104.78 81.28,103.5 C7.1 | C4.1 48.26,57.78 38.74,57.78 E4.5 31.12,65.41 20.96,65.41 17.15,69.22 17.15,72.39 15.88,73.66 13.97,73.66 EDGE.BA2 | E3.16 78.74,43.18 77.47,44.45 77.47,50.16 72.39,55.24 R6.1

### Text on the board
Bottom: VRS | TU10 COMMAND BUFFERS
